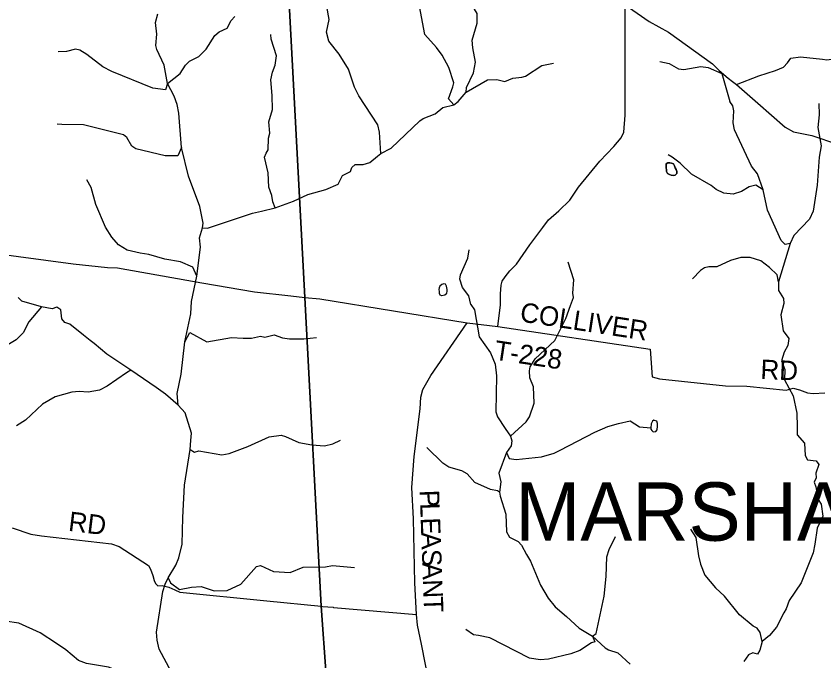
# Model space of a CAD drawing. Extents: x 1525783 to 1900577, y 218250 to 627376.
# Drawn here: x 1673832 to 1686297, y 405810 to 415754 of the extents above; entities that cross this region are included whole.
import ezdxf

# ---------------------------------------------------------------- set-up
doc = ezdxf.new("R2010")
doc.units = 0
for name, color, linetype in [('GM_X_County_Road', 7, 'Continuous'), ('GM_X_County_Road_Text', 7, 'Continuous'), ('GM_X_Minor_Lake', 7, 'Continuous'), ('GM_X_Minor_River', 7, 'Continuous'), ('GM_X_Township', 7, 'Continuous'), ('GM_X_Township_Road', 7, 'Continuous'), ('GM_X_Township_Road_Text', 7, 'Continuous'), ('GM_X_Township_Text', 7, 'Continuous')]:
    doc.layers.add(name, color=color, linetype=linetype)

msp = doc.modelspace()

# ---------------------------------------------------------------- linework, layer by layer
at = {"layer": 'GM_X_County_Road'}
for points in [[(1680207, 405468), (1680086, 406067), (1680027, 406359), (1680012, 406526), (1679985, 407012), (1679963, 407998), (1679937, 408486), (1679972, 408962), (1680068, 409697), (1680079, 409877), (1680106, 409994), (1680233, 410212), (1680793, 411023), (1681268, 410968), (1681309, 411303), (1681307, 411469), (1681318, 411603), (1681334, 411668), (1681377, 411736), (1681453, 411824), (1681555, 411928), (1681759, 412226), (1681960, 412497), (1682050, 412613), (1682207, 412751), (1682376, 412917), (1682513, 413118), (1682839, 413520), (1683056, 413746), (1683170, 413879), (1683210, 413963), (1683233, 414229), (1683229, 415931)], [(1683229, 415931), (1683600, 415673), (1683898, 415507), (1684581, 415018), (1684679, 414918), (1684821, 414800), (1684888, 414749), (1684947, 414698), (1685278, 414411), (1685698, 414044), (1685829, 413971), (1686112, 413914), (1686509, 413780), (1686769, 413685), (1687024, 413547), (1687879, 413021), (1688235, 412775)]]:
    msp.add_lwpolyline(points, dxfattribs=at)
at = {"layer": 'GM_X_Minor_Lake'}
for points in [[(1684000, 413414), (1683992, 413446), (1683976, 413475), (1683948, 413485), (1683922, 413491), (1683890, 413491), (1683864, 413475), (1683864, 413442), (1683866, 413416), (1683868, 413384)], [(1683868, 413384), (1683866, 413416), (1683864, 413442), (1683864, 413475), (1683890, 413491), (1683922, 413491), (1683948, 413485), (1683976, 413475), (1683992, 413446), (1684000, 413414), (1684016, 413388), (1684028, 413360), (1684030, 413330), (1684000, 413302), (1683972, 413296), (1683942, 413300), (1683914, 413310), (1683886, 413330), (1683868, 413356), (1683868, 413384)], [(1683868, 413384), (1683868, 413356), (1683886, 413330), (1683914, 413310), (1683942, 413300), (1683972, 413296), (1684000, 413302), (1684030, 413330), (1684028, 413360), (1684016, 413388), (1684000, 413414)], [(1680432, 411627), (1680400, 411615), (1680372, 411590), (1680362, 411564), (1680356, 411538), (1680360, 411509), (1680358, 411483), (1680370, 411456), (1680398, 411444), (1680400, 411444)], [(1680400, 411444), (1680450, 411456), (1680476, 411479), (1680482, 411511), (1680482, 411540), (1680480, 411566), (1680472, 411592), (1680460, 411621), (1680432, 411627), (1680400, 411615), (1680372, 411590), (1680362, 411564), (1680356, 411538), (1680360, 411509), (1680358, 411483), (1680370, 411456), (1680398, 411444), (1680400, 411444)], [(1680400, 411444), (1680450, 411456), (1680476, 411479), (1680482, 411511), (1680482, 411540), (1680480, 411566), (1680472, 411592), (1680460, 411621), (1680432, 411627)], [(1683625, 409406), (1683625, 409384), (1683641, 409365), (1683665, 409343), (1683705, 409346), (1683727, 409374), (1683732, 409428), (1683731, 409472), (1683719, 409505), (1683685, 409519), (1683673, 409523), (1683655, 409509), (1683634, 409464)], [(1683634, 409464), (1683625, 409406)]]:
    msp.add_lwpolyline(points, dxfattribs=at)
at = {"layer": 'GM_X_Minor_River'}
for points in [[(1680776, 414583), (1680782, 414653), (1680890, 414880), (1680923, 415044), (1680879, 415265), (1680871, 415385), (1680948, 415645), (1680945, 415797), (1680908, 415864), (1680716, 416022), (1680665, 416147), (1680565, 416309), (1680429, 416512)], [(1680587, 414387), (1680504, 414477), (1680572, 414664), (1680585, 414728), (1680509, 414960), (1680406, 415153), (1680318, 415270), (1680138, 415474), (1680003, 416184)], [(1679460, 413634), (1679438, 413964), (1679414, 414078), (1679122, 414527), (1679052, 414660), (1678963, 414935), (1678819, 415166), (1678656, 415371), (1678619, 415508), (1678665, 415704), (1678628, 415903)], [(1676538, 411351), (1676621, 411745), (1676679, 412189), (1676659, 412334), (1676710, 412490), (1676716, 412560), (1676666, 412820), (1676494, 413284), (1676384, 413727), (1676342, 414259), (1676318, 414392), (1676273, 414521), (1676166, 414714), (1676115, 414997), (1676001, 415242), (1675985, 415304), (1676002, 415477), (1675983, 415659), (1676019, 415791)], [(1676166, 414714), (1676361, 414869), (1676445, 414998), (1676509, 415059), (1676652, 415134), (1676764, 415247), (1676896, 415455), (1676963, 415514), (1677088, 415570), (1677151, 415686), (1677206, 415747)], [(1677831, 412800), (1677791, 412889), (1677780, 412989), (1677731, 413118), (1677719, 413337), (1677663, 413581), (1677688, 413643), (1677719, 413694), (1677724, 413873), (1677746, 413948), (1677731, 414127), (1677787, 414317), (1677784, 414529), (1677763, 414771), (1677787, 414892), (1677831, 415000), (1677851, 415140), (1677768, 415402), (1677761, 415473)], [(1676166, 414714), (1676136, 414616), (1675943, 414645), (1675311, 414901), (1675168, 414973), (1674925, 415162), (1674816, 415228), (1674746, 415247), (1674611, 415209), (1674479, 415204)], [(1676710, 412490), (1676784, 412483), (1677481, 412715), (1677616, 412745), (1677831, 412800), (1678111, 412899), (1678335, 413002), (1678613, 413081), (1678801, 413162), (1678867, 413295), (1678992, 413358), (1679014, 413419), (1679066, 413467), (1679189, 413466), (1679291, 413499), (1679407, 413595), (1679460, 413634), (1679620, 413716), (1680062, 414140), (1680112, 414177), (1680296, 414246), (1680418, 414346), (1680587, 414387), (1680656, 414440), (1680776, 414583), (1681108, 414770), (1681252, 414779), (1681376, 414747), (1681499, 414799), (1681637, 414811), (1681694, 414830), (1681943, 414992), (1682124, 415031)], [(1683764, 415055), (1683908, 415025), (1684056, 414942), (1684136, 414932), (1684401, 414978), (1684513, 414964), (1684722, 414872), (1684847, 414439)], [(1685778, 412246), (1685699, 412231), (1685637, 412295), (1685429, 412760), (1685362, 413074), (1685275, 413320), (1685181, 413442), (1684919, 413999), (1684897, 414110), (1684906, 414294), (1684892, 414372), (1684847, 414439)], [(1686220, 414405), (1686226, 414234), (1686205, 414036), (1686257, 413754), (1686224, 413580), (1686192, 413149), (1686130, 412749), (1686076, 412622), (1685836, 412371), (1685778, 412246), (1685596, 411658), (1685596, 411523), (1685674, 411399), (1685682, 411323)], [(1676384, 413727), (1676326, 413602), (1676132, 413601), (1675679, 413707), (1675616, 413750), (1675540, 413882), (1675489, 413923), (1674873, 414076), (1674537, 414081), (1674465, 414089)], [(1684896, 413008), (1684756, 413024), (1684633, 413083), (1684560, 413142), (1684253, 413318), (1684082, 413487), (1683958, 413580), (1683894, 413617)], [(1676621, 411745), (1676557, 411885), (1676370, 411966), (1676129, 412006), (1675882, 412079), (1675748, 412101), (1675545, 412145), (1675410, 412227), (1675308, 412347), (1675209, 412499), (1675061, 412851), (1674992, 413113), (1674924, 413232)], [(1685362, 413074), (1685246, 413150), (1685143, 413120), (1685027, 413048), (1684896, 413008)], [(1680848, 411306), (1680818, 411439), (1680720, 411571), (1680678, 411696), (1680687, 411762), (1680804, 412021), (1680822, 412151)], [(1684855, 411986), (1684644, 411889), (1684522, 411889), (1684455, 411872), (1684392, 411831), (1684268, 411705)], [(1685596, 411658), (1685576, 411764), (1685460, 411877), (1685326, 411979), (1685160, 412031), (1685014, 412031), (1684855, 411986)], [(1682388, 411289), (1682435, 411415), (1682424, 411484), (1682440, 411688), (1682351, 411958)], [(1674872, 410832), (1674658, 411003), (1674582, 411030), (1674539, 411087), (1674523, 411223), (1674459, 411266), (1674386, 411241), (1674222, 411271), (1673918, 411357), (1673861, 411414)], [(1674222, 411271), (1674025, 411039), (1673940, 410869), (1673831, 410763), (1673491, 410562), (1673239, 410421), (1672897, 410185), (1672695, 409914), (1672645, 409881), (1672544, 409832), (1672477, 409773), (1672409, 409637), (1672257, 409539), (1672208, 409487), (1672171, 409418), (1672107, 409212), (1672044, 409147)], [(1676331, 409756), (1676317, 409936), (1676377, 410234), (1676437, 410729), (1676526, 411164), (1676538, 411351)], [(1680848, 411306), (1680907, 411223), (1680978, 410807), (1681150, 410563), (1681224, 410385), (1681244, 410205), (1681235, 409653), (1681262, 409575), (1681380, 409395), (1681461, 409276), (1681480, 409203), (1681471, 409127), (1681400, 409024), (1681282, 408705), (1681310, 408570), (1681292, 408414), (1681303, 408348), (1681388, 408070), (1681401, 407801), (1681448, 407720), (1681578, 407649), (1681633, 407596), (1681706, 407451), (1681769, 407348), (1681923, 406977), (1682043, 406775), (1682150, 406641), (1682324, 406495), (1682523, 406312), (1682726, 406191), (1682920, 406012), (1682972, 405980), (1683120, 405932), (1683309, 405757)], [(1681461, 409276), (1681704, 409499), (1681756, 409575), (1681824, 409787), (1681817, 410039), (1681761, 410178), (1681754, 410283), (1681767, 410346), (1681841, 410468), (1682147, 410751), (1682316, 411093), (1682388, 411289)], [(1685682, 411323), (1685634, 411149), (1685671, 410901), (1685759, 410783), (1685742, 410675), (1685686, 410570), (1685643, 410440), (1685697, 410303), (1685691, 410147), (1685821, 409897), (1685880, 409632), (1685885, 409419), (1685886, 409295), (1686000, 409166), (1686011, 408979), (1686045, 408913), (1686178, 408897), (1686222, 408840), (1686172, 408705), (1686181, 408634), (1686150, 408567), (1686171, 408496), (1686211, 408298), (1686254, 408227), (1686281, 408044), (1686193, 407857), (1686157, 407611), (1686132, 407477), (1685946, 407011), (1685760, 406739), (1685714, 406613), (1685681, 406552), (1685565, 406327), (1685457, 406202), (1685346, 406109), (1685310, 405974), (1685271, 405914), (1685199, 405931), (1685135, 405904), (1685061, 405799)], [(1676437, 410729), (1676513, 410876), (1676776, 410732), (1677154, 410798), (1677334, 410788), (1677465, 410788), (1677603, 410819), (1677669, 410802), (1677816, 410838), (1677944, 410794), (1678048, 410779), (1678271, 410778), (1678466, 410796)], [(1675600, 410293), (1675233, 410541), (1675034, 410706), (1674976, 410749), (1674872, 410832)], [(1675600, 410293), (1675536, 410251), (1675237, 410046), (1675118, 409987), (1674943, 409953), (1674806, 409965), (1674690, 409956), (1674436, 409883), (1674240, 409767), (1673976, 409522), (1673837, 409433)], [(1676528, 409208), (1676538, 409320), (1676442, 409634), (1676331, 409756), (1676138, 409924), (1675991, 410028), (1675600, 410293)], [(1681400, 409024), (1681443, 408933), (1681551, 408918), (1681941, 408957), (1682134, 409011), (1682229, 409058), (1682764, 409338), (1682962, 409424), (1683129, 409472), (1683310, 409510), (1683451, 409422), (1683625, 409406)], [(1676515, 409070), (1676585, 409029), (1676653, 409048), (1677006, 408990), (1677118, 409006), (1677408, 409115), (1677737, 409263), (1677922, 409289), (1677990, 409272), (1678194, 409178), (1678394, 409143), (1678590, 409129), (1678717, 409157), (1678838, 409216)], [(1676229, 405635), (1676040, 405991), (1676008, 406129), (1675999, 406252), (1676095, 406878), (1676133, 406994), (1676176, 407089), (1676295, 407286), (1676344, 407400), (1676395, 407612), (1676406, 408021), (1676432, 408520), (1676515, 409070), (1676528, 409208)], [(1681292, 408414), (1681260, 408434), (1681150, 408454), (1680913, 408561), (1680794, 408695), (1680712, 408742), (1680508, 408800), (1680417, 408858), (1680169, 409103)], [(1684237, 407843), (1684319, 407711), (1684362, 407428), (1684393, 407301), (1684461, 407134), (1684625, 406934), (1684762, 406806)], [(1682726, 406191), (1682783, 406231), (1682908, 406808), (1682940, 407109), (1682949, 407415), (1682983, 407529), (1683082, 407728)], [(1676176, 407089), (1676215, 407013), (1676355, 406913), (1676536, 406947), (1676688, 406955), (1676890, 406888), (1677087, 406894), (1677298, 406992), (1677543, 407267), (1677601, 407280), (1677802, 407188), (1678063, 407173), (1678261, 407256), (1678604, 407258), (1678714, 407281), (1679055, 407251)], [(1685346, 406109), (1685313, 406248), (1685270, 406315), (1685207, 406344), (1684993, 406521), (1684762, 406806)], [(1676500, 405325), (1676336, 405354), (1676199, 405341), (1676035, 405379), (1675452, 405637), (1675259, 405712), (1674918, 405770), (1674792, 405813), (1674600, 405980), (1674457, 406076), (1674200, 406244), (1673874, 406390), (1673662, 406421)], [(1682726, 406191), (1682763, 406103), (1682709, 406089), (1682529, 405971), (1682394, 405917), (1682046, 405835), (1681921, 405828), (1681755, 405850), (1681143, 406163), (1680966, 406199), (1680892, 406212), (1680771, 406291)]]:
    msp.add_lwpolyline(points, dxfattribs=at)
at = {"layer": 'GM_X_Township'}
for points in [[(1699164, 420184), (1695772, 414672), (1695360, 414002), (1694863, 409438), (1694651, 408579), (1692963, 401404), (1692960, 401391), (1692916, 400719), (1692619, 395862), (1688475, 399440), (1688322, 399564), (1688208, 399673), (1687479, 400030), (1682729, 402947), (1680396, 404440), (1678915, 405396), (1678615, 405583), (1678537, 406652), (1678285, 411417), (1677923, 418276)], [(1677923, 418276), (1678285, 411417), (1678537, 406652), (1678615, 405583)]]:
    msp.add_lwpolyline(points, dxfattribs=at)
at = {"layer": 'GM_X_Township_Road'}
for points in [[(1684947, 414698), (1685292, 414832), (1685549, 414918), (1685672, 414968), (1685738, 415034), (1685790, 415109), (1685938, 415126), (1686274, 415092), (1686342, 415082), (1686454, 415094), (1686489, 415454), (1686651, 416873), (1686742, 417655), (1686764, 417733), (1687056, 417730), (1687274, 417707), (1687376, 417716), (1687467, 417811), (1687674, 418187), (1688289, 419091), (1688579, 419532), (1688747, 419737), (1688884, 419862), (1689016, 419921)], [(1672358, 412281), (1673440, 412106), (1674710, 411933), (1675243, 411878), (1675395, 411870), (1676700, 411642), (1677511, 411500), (1678069, 411441), (1678070, 411440)], [(1678070, 411440), (1678285, 411417), (1678516, 411393), (1680793, 411023)], [(1681268, 410968), (1683617, 410616), (1683649, 410192), (1683762, 410161), (1684777, 410054), (1685108, 410048), (1685713, 409987), (1685823, 410014), (1685919, 409991), (1686044, 409945), (1686134, 409932), (1686312, 409945)], [(1673772, 407863), (1674059, 407765), (1674223, 407739), (1675303, 407617), (1675422, 407574), (1675872, 407282), (1675906, 407222), (1675940, 407124), (1675961, 407051), (1675981, 407003), (1676017, 406969), (1676085, 406973), (1676190, 406946), (1676282, 406906), (1676358, 406868), (1677700, 406735), (1677701, 406735)], [(1677701, 406735), (1678537, 406652), (1678561, 406650), (1678725, 406636), (1678728, 406635)], [(1678728, 406635), (1680012, 406526)]]:
    msp.add_lwpolyline(points, dxfattribs=at)

# ---------------------------------------------------------------- texts
at = {"layer": 'GM_X_County_Road_Text'}
for s, rotation, p in [('P', 272.1005, (1680059, 408442)), ('L', 272.1005, (1680066, 408240)), ('E', 272.1005, (1680074, 408016)), ('A', 272.1003, (1680082, 407791)), ('S', 272.1005, (1680092, 407528)), ('A', 272.1003, (1680099, 407325)), ('N', 272.0987, (1680109, 407062)), ('T', 272.0876, (1680119, 406798))]:
    msp.add_text(s, height=300, rotation=rotation, dxfattribs=at).set_placement(p)
at = {"layer": 'GM_X_Township_Road_Text'}
for s, rotation, p in [('COLLIVER', 351.3384, (1681595, 411047)), ('T-228', 351.5114, (1681197, 410459)), ('RD', 357.5314, (1685314, 410159)), ('RD', 353.0589, (1674627, 407817))]:
    msp.add_text(s, height=300, rotation=rotation, dxfattribs=at).set_placement(p)
at = {"layer": 'GM_X_Township_Text'}
msp.add_text('MARSHALL', height=900, rotation=0, dxfattribs=at).set_placement((1681536, 407663))

doc.saveas('drawing.dxf')
